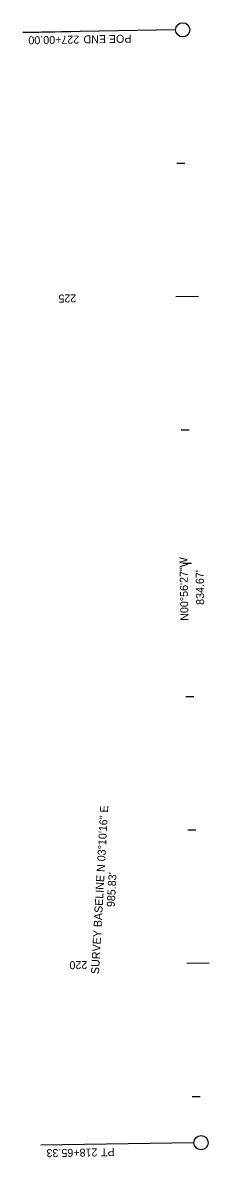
# Model space of a CAD drawing. Extents: x 1801895 to 1805049, y 572742 to 575010.
# Drawn here: x 1803400 to 1803540, y 574159 to 575010 of the extents above; entities that cross this region are included whole.
import ezdxf

# ---------------------------------------------------------------- set-up
doc = ezdxf.new("R2010")
doc.units = 0
for name, color, linetype in [('_CIVIL_CONSTRUCTION', 7, 'Continuous'), ('DSN_DRFT_Named-Boundary', 7, 'Continuous'), ('DSN_RDWY_Alignment Annotation', 7, 'Continuous'), ('DSN_ROW_Point-Annotation', 7, 'Continuous')]:
    doc.layers.add(name, color=color, linetype=linetype)

msp = doc.modelspace()

# ---------------------------------------------------------------- linework, layer by layer
at = {"layer": '_CIVIL_CONSTRUCTION'}
msp.add_circle((1803527.31, 574587.6), 0.05, dxfattribs=at)
at = {"layer": 'DSN_RDWY_Alignment Annotation'}
for p, q in [((1803515.11, 575004.79), (1803400.47, 575002.9)), ((1803520.45, 575004.88), (1803520.45, 575004.88)), ((1803400.47, 575002.9), (1803436.47, 575003.5)), ((1803516.1, 574904.79), (1803522.1, 574904.89)), ((1803515.34, 574804.76), (1803532.14, 574805.04)), ((1803519.38, 574704.82), (1803525.38, 574704.92)), ((1803521.02, 574604.83), (1803527.02, 574604.93)), ((1803522.67, 574504.84), (1803528.66, 574504.94)), ((1803524.31, 574404.86), (1803530.31, 574404.96)), ((1803523.55, 574304.83), (1803540.35, 574305.11)), ((1803527.59, 574204.88), (1803533.59, 574204.98)), ((1803528.82, 574170.23), (1803414.18, 574168.35)), ((1803414.18, 574168.35), (1803414.18, 574168.35)), ((1803534.16, 574170.32), (1803534.16, 574170.32))]:
    msp.add_line(p, q, dxfattribs=at)
for centre in [(1803520.45, 575004.88), (1803534.16, 574170.32)]:
    msp.add_circle(centre, 5.34, dxfattribs=at)

# ---------------------------------------------------------------- texts
at = {"layer": 'DSN_DRFT_Named-Boundary'}
for s, p in [('SURVEY BASELINE N 03°10\'16" E', (1803457.63, 574296.61)), ("985.83'", (1803469.43, 574346.86))]:
    msp.add_text(s, height=6, rotation=86.82901, dxfattribs=at).set_placement(p)
at = {"layer": 'DSN_RDWY_Alignment Annotation'}
for s, rotation, p in [('227+00.00', 180.94083, (1803442.82, 575000.6)), ('END', 180.94083, (1803462.86, 575000.93)), ('POE ', 180.94083, (1803481.94, 575001.24)), ('225', 180.94083, (1803440.59, 574806.54)), ('N00°56\'27"W', 90.94083, (1803524.73, 574561.75)), ('220', 180.94083, (1803448.88, 574306.61)), ('218+65.33', 180.94083, (1803456.43, 574166.04)), ('PT', 180.94083, (1803469.36, 574166.26))]:
    msp.add_text(s, height=6, rotation=rotation, dxfattribs=at).set_placement(p)
at = {"layer": 'DSN_ROW_Point-Annotation'}
msp.add_text("834.67'", height=6, rotation=90.94083, dxfattribs=at).set_placement((1803536.54, 574573.67))

doc.saveas('drawing.dxf')
